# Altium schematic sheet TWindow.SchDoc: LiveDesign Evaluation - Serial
size A3; Organization: Altium Limited; Address1: L3, 12a Rodborough Rd; Address2: Frenchs Forest; Address3: NSW; Address4: Australia 2086; DocumentNumber: 7; SheetNumber: 7; SheetTotal: 7
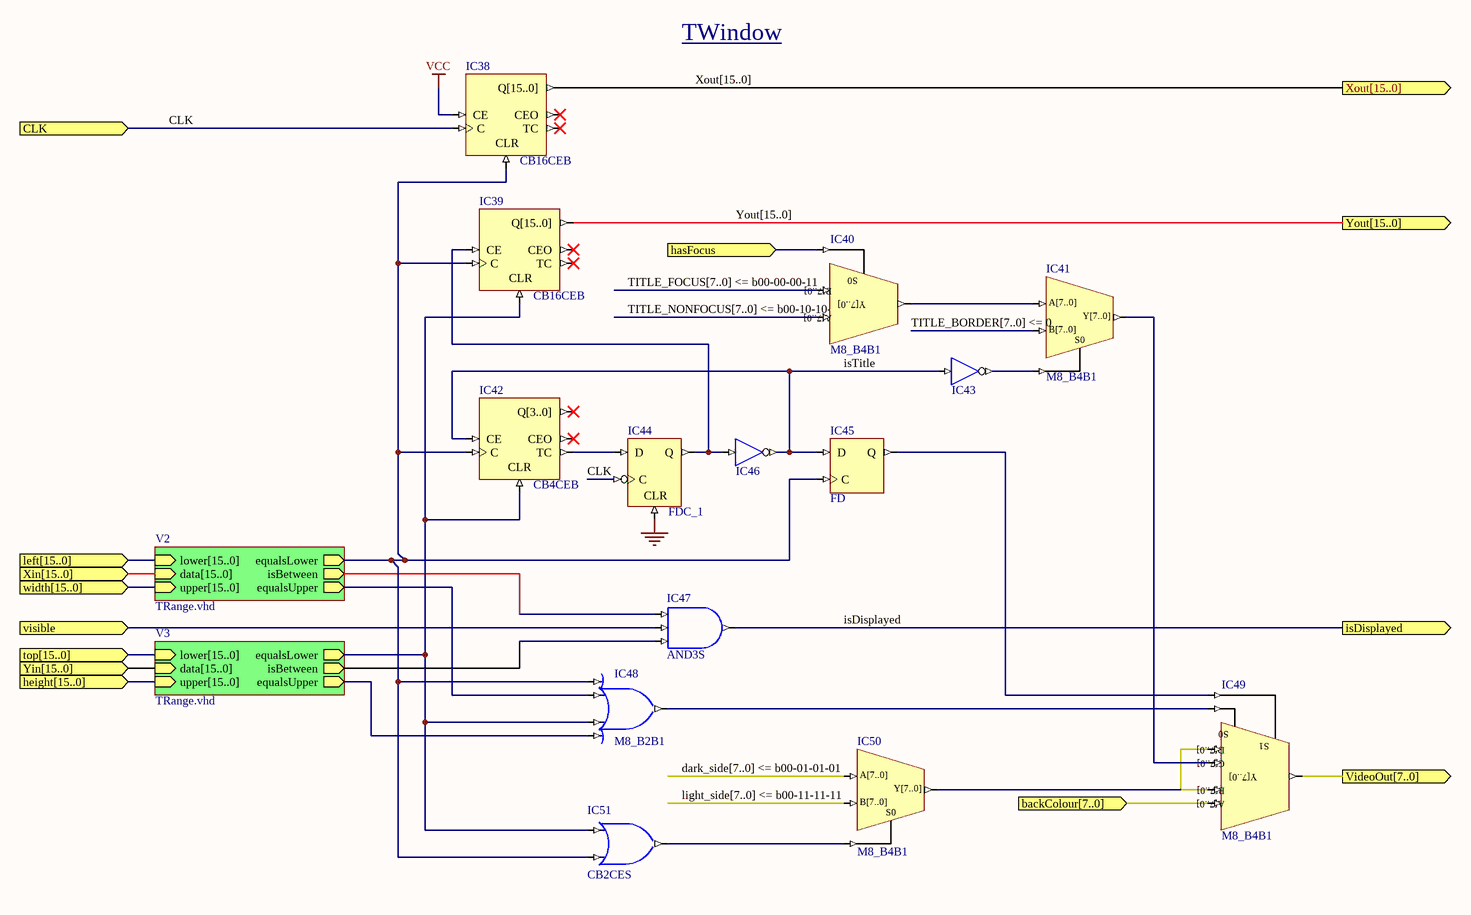
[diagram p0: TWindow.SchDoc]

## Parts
IC38  CB16CEB
IC39  CB16CEB
IC40  M8_B4B1
IC41  M8_B4B1
IC42  CB4CEB
IC43  INV  (value not drawn)
IC44  FDC_1
IC45  FD
IC46  INV  (value not drawn)
IC47  AND3S
IC48  M8_B2B1
IC49  M8_B4B1
IC50  M8_B4B1
IC51  CB2CES

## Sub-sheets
V2 = TRange.vhd: lower[15..0] (in), data[15..0] (in), upper[15..0] (in), isBetween (out), equalsLower (out), equalsUpper (out)
V3 = TRange.vhd: lower[15..0] (in), data[15..0] (in), upper[15..0] (in), isBetween (out), equalsLower (out), equalsUpper (out)

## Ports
backColour[7..0] (in), CLK (in), hasFocus (in), height[15..0] (in), isDisplayed (out), left[15..0] (in), top[15..0] (in), VideoOut[7..0] (out), visible (in), width[15..0] (in), Xin[15..0] (in), Xout[15..0] (out), Yin[15..0] (in), Yout[15..0] (out)

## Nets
GND: IC44.CLR
VCC: IC38.CE
CLK: IC38.C IC44.C ; port CLK
hasFocus: IC40.S0 ; port hasFocus
isDisplayed: IC47.O ; port isDisplayed
isTitle: IC42.CE IC43.I IC45.D IC46.O
visible: IC47.I1 ; port visible
NetIC38_CLR: IC38.CLR IC39.C IC42.C IC45.C IC48.I0 IC51.I1 ; sheet V2/equalsLower
NetIC39_CE: IC39.CE IC44.Q IC46.I
NetIC39_CLR: IC39.CLR IC42.CLR IC48.I2 IC51.I0 ; sheet V3/equalsLower
NetIC41_S0: IC41.S0 IC43.O
NetIC42_TC: IC42.TC IC44.D
NetIC45_Q: IC45.Q IC49.S1
NetIC47_I0: IC47.I0 ; sheet V2/isBetween
NetIC47_I2: IC47.I2 ; sheet V3/isBetween
NetIC48_I1: IC48.I1 ; sheet V2/equalsUpper
NetIC48_I3: IC48.I3 ; sheet V3/equalsUpper
NetIC48_O: IC48.O IC49.S0
NetIC50_S0: IC50.S0 IC51.O

Not connected (* = marked no-connect by the designer): IC38 CEO* Q[15..0] TC*; IC39 CEO* Q[15..0] TC*; IC40 A[7..0] B[7..0] Y[7..0]; IC41 A[7..0] B[7..0] Y[7..0]; IC42 CEO* Q[3..0]*; IC49 A[7..0] B[7..0] C[7..0] D[7..0] Y[7..0]; IC50 A[7..0] B[7..0] Y[7..0]

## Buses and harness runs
bus dark_side[7..0] <= b00-01-01-01
bus light_side[7..0] <= b00-11-11-11
bus port height[15..0] = sheet V3/upper[15..0]
bus port left[15..0] = sheet V2/lower[15..0]
bus port top[15..0] = sheet V3/lower[15..0]
bus port width[15..0] = sheet V2/upper[15..0]
bus port Xin[15..0] = sheet V2/data[15..0]
bus port Yin[15..0] = sheet V3/data[15..0]
bus TITLE_BORDER[7..0] <= 0
bus TITLE_FOCUS[7..0] <= b00-00-00-11
bus TITLE_NONFOCUS[7..0] <= b00-10-10-10
bus Xout[15..0] = port Xout[15..0]
bus Yout[15..0] = port Yout[15..0]

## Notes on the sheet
- TWindow

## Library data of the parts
IC38 IC39 = CB16CEB: 16-Bit Cascadable Binary Counters with Clock Enable and Asynchronous Clear, Bus Version; Xilinx Equivalent: CB16CE; ArchiveName: GENERIC; VHDLIB_SIM: GENERIC_LIB
IC40 IC41 IC50 = M8_B2B1: 2x8-Bit Bus to 1x8-Bit Bus Multiplexer; ArchiveName: GENERIC; VHDLIB_SIM: GENERIC_LIB
IC42 = CB4CEB: 4-Bit Cascadable Binary Counters with Clock Enable and Asynchronous Clear, Bus Version; ArchiveName: GENERIC; VHDLIB_SIM: GENERIC_LIB
IC43 IC46 = INV: Inverter; ArchiveName: GENERIC; VHDLIB_SIM: GENERIC_LIB
IC44 = FDC_1: D-Type Negative Edge Flip-Flop with Asynchronous Clear; ArchiveName: GENERIC; VHDLIB_SIM: GENERIC_LIB
IC45 = FD: D-Type Flip-Flop; ArchiveName: GENERIC; VHDLIB_SIM: GENERIC_LIB
IC47 = AND3S: 3-Input AND Gate, Single Pin Version; Xilinx Equivalent: AND3; ArchiveName: GENERIC; VHDLIB_SIM: GENERIC_LIB
IC48 = OR4S: 4-Input OR Gate, Single Pin Version; Xilinx Equivalent: OR4; ArchiveName: GENERIC; VHDLIB_SIM: GENERIC_LIB
IC49 = M8_B4B1: 4x8-Bit Bus to 1x8-Bit Bus Multiplexer; ArchiveName: GENERIC; VHDLIB_SIM: GENERIC_LIB
IC51 = OR2S: 2-Input OR Gate, Single Pin Version; Xilinx Equivalent: OR2; ArchiveName: GENERIC; VHDLIB_SIM: GENERIC_LIB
